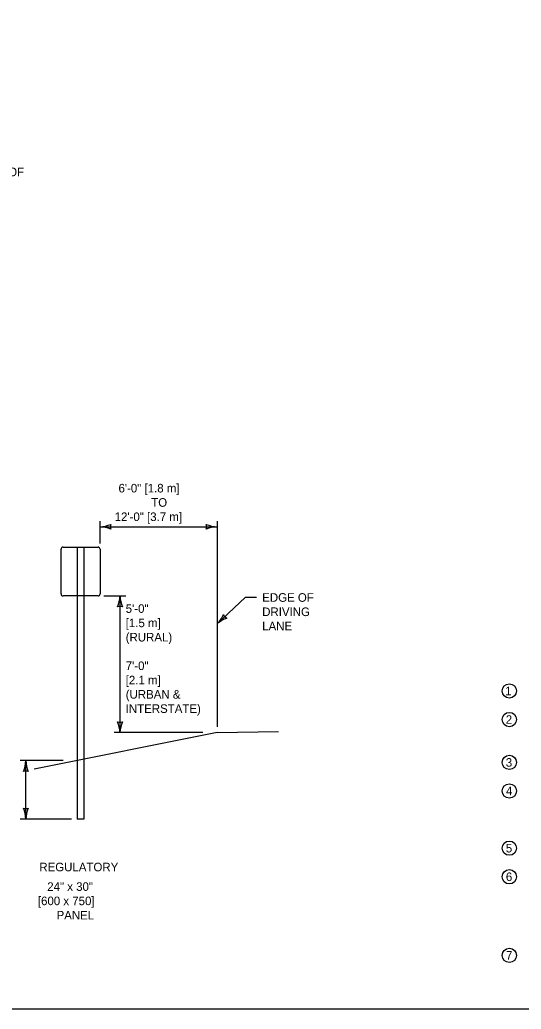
# Model space of a CAD drawing. Extents: x 49991.4 to 50021, y 49987.6 to 50011.4.
# Drawn here: x 50005.11 to 50008.62, y 49987.8 to 49994.72 of the extents above; entities that cross this region are included whole.
import ezdxf

# ---------------------------------------------------------------- set-up
doc = ezdxf.new("R2010")
doc.units = 0
for name, color, linetype in [('Level 1', 7, 'Continuous'), ('Level 2', 7, 'Continuous'), ('Level 3', 7, 'Continuous'), ('Level 4', 7, 'Continuous')]:
    doc.layers.add(name, color=color, linetype=linetype)

msp = doc.modelspace()

# ---------------------------------------------------------------- linework, layer by layer
at = {"layer": 'Level 1'}
for p, q in [((50005.4008, 49990.7041), (50005.4008, 49991.0171)), ((50005.415, 49991.0313), (50005.6598, 49991.0313)), ((50005.5148, 49991.0313), (50005.5148, 49989.5383)), ((50005.5602, 49991.0313), (50005.5602, 49989.5474)), ((50005.674, 49991.0171), (50005.674, 49990.7041)), ((50005.5148, 49990.6899), (50005.415, 49990.6899)), ((50005.6598, 49990.6899), (50005.5602, 49990.6899)), ((50006.4934, 49989.7339), (50005.2121, 49989.4777)), ((50006.4934, 49989.7339), (50006.922, 49989.7426))]:
    msp.add_line(p, q, dxfattribs=at)
msp.add_lwpolyline([(49999.3835, 49998.9992), (50016.7501, 49998.9992), (50016.7501, 49987.7988), (49999.3835, 49987.7988)], close=True, dxfattribs=at)
for centre, major_axis, start_param, end_param in [((50005.415, 49991.0171), (-0.0142, 0), 4.712389, 6.283185), ((50005.6598, 49991.0171), (-0.0142, 0), 3.141593, 4.712389), ((50005.415, 49990.7041), (0.0142, 0), 3.141593, 4.712389), ((50005.6598, 49990.7041), (0.0142, 0), 4.712389, 6.283185)]:
    msp.add_ellipse(centre, major_axis=major_axis, ratio=0.999996, start_param=start_param, end_param=end_param, dxfattribs=at)
at = {"layer": 'Level 2'}
for centre in [(50008.5389, 49990.0253), (50008.5389, 49989.8253), (50008.5389, 49989.5253), (50008.5389, 49989.3253), (50008.5389, 49988.9253), (50008.5389, 49988.7253), (50008.5389, 49988.1753)]:
    msp.add_circle(centre, 0.05, dxfattribs=at)
at = {"layer": 'Level 3'}
for p, q in [((50005.674, 49991.0571), (50005.674, 49991.2138)), ((50005.674, 49991.1738), (50006.4934, 49991.1738)), ((50006.4934, 49991.2138), (50006.4934, 49989.7739)), ((50005.6998, 49990.6899), (50005.8534, 49990.6899)), ((50005.8134, 49990.6899), (50005.8134, 49989.7339)), ((50006.6888, 49990.679), (50006.4934, 49990.4945)), ((50006.7688, 49990.679), (50006.6888, 49990.679)), ((50006.3934, 49989.7339), (50005.7734, 49989.7339)), ((50005.4148, 49989.5383), (50005.1146, 49989.5383)), ((50005.1546, 49989.1285), (50005.1546, 49989.5383)), ((50005.4748, 49989.1285), (50005.1146, 49989.1285))]:
    msp.add_line(p, q, dxfattribs=at)
for centre, radius, start, end in [((50005.6648, 49991.3959), 0.2223, 272.36048, 292.54399), ((50005.6625, 49990.941), 0.233, 67.92284, 87.17269), ((50005.8022, 49991.1738), 0.0548, 162.13882, 197.86118), ((50006.3652, 49991.1738), 0.0548, 342.13882, 17.86118), ((50006.5049, 49991.4065), 0.233, 247.92284, 267.17269), ((50006.5026, 49990.9516), 0.2223, 92.36048, 112.54399), ((50005.5807, 49990.7014), 0.233, 337.92284, 357.17269), ((50006.0356, 49990.699), 0.2223, 182.36048, 202.54399), ((50005.8134, 49990.5616), 0.0548, 72.13882, 107.86118), ((50006.3343, 49990.6497), 0.2223, 315.7076, 335.89111), ((50006.6448, 49990.3173), 0.233, 111.26996, 130.51981), ((50006.5866, 49990.5825), 0.0548, 205.48594, 241.2083), ((50005.5913, 49989.7247), 0.2223, 2.36048, 22.54399), ((50005.8134, 49989.8621), 0.0548, 252.13882, 287.86118), ((50006.0461, 49989.7224), 0.233, 157.92284, 177.17269), ((50004.9219, 49989.5498), 0.233, 337.92284, 357.17269), ((50005.3767, 49989.5475), 0.2223, 182.36048, 202.54399), ((50005.1546, 49989.4101), 0.0548, 72.13882, 107.86118), ((50004.9325, 49989.1194), 0.2223, 2.36048, 22.54399), ((50005.1546, 49989.2567), 0.0548, 252.13882, 287.86118), ((50005.3873, 49989.117), 0.233, 157.92284, 177.17269)]:
    msp.add_arc(centre, radius, start, end, dxfattribs=at)
at = {"layer": 'Level 4'}
for p, q in [((50005.5602, 49990.6899), (50005.5148, 49990.6899)), ((50005.5148, 49989.5383), (50005.5148, 49989.1286)), ((50005.5602, 49989.5474), (50005.5602, 49989.1286)), ((50005.5602, 49989.1286), (50005.5148, 49989.1286))]:
    msp.add_line(p, q, dxfattribs=at)

# ---------------------------------------------------------------- texts
at = {"layer": 'Level 2'}
for s, p in [('EDGE OF', (50004.781, 49993.6262)), ('6\'-0" [1.8 m]', (50005.8029, 49991.4138)), ('TO', (50006.032, 49991.3138)), ('12\'-0" [3.7 m]', (50005.776, 49991.2138)), ('EDGE OF', (50006.8088, 49990.649)), ('5\'-0"', (50005.8534, 49990.5714)), ('DRIVING', (50006.8088, 49990.549)), ('[1.5 m]', (50005.8534, 49990.4714)), ('LANE', (50006.8088, 49990.449)), ('(RURAL)', (50005.8534, 49990.3714)), ('7\'-0"', (50005.8534, 49990.1714)), ('[2.1 m]', (50005.8534, 49990.0714)), ('1', (50008.5097, 49989.9954)), ('(URBAN &', (50005.8534, 49989.9714)), ('INTERSTATE)', (50005.8534, 49989.8714)), ('2', (50008.5137, 49989.7953)), ('3', (50008.5137, 49989.4953)), ('4', (50008.5149, 49989.2953)), ('5', (50008.514, 49988.8953)), ('REGULATORY', (50005.2488, 49988.7634)), ('6', (50008.5144, 49988.6953)), ('24" x 30"', (50005.3042, 49988.6266)), ('[600 x 750]', (50005.2386, 49988.5266)), ('PANEL', (50005.3696, 49988.4266)), ('7', (50008.5151, 49988.1453))]:
    msp.add_text(s, height=0.06, dxfattribs=at).set_placement(p)

doc.saveas('drawing.dxf')
